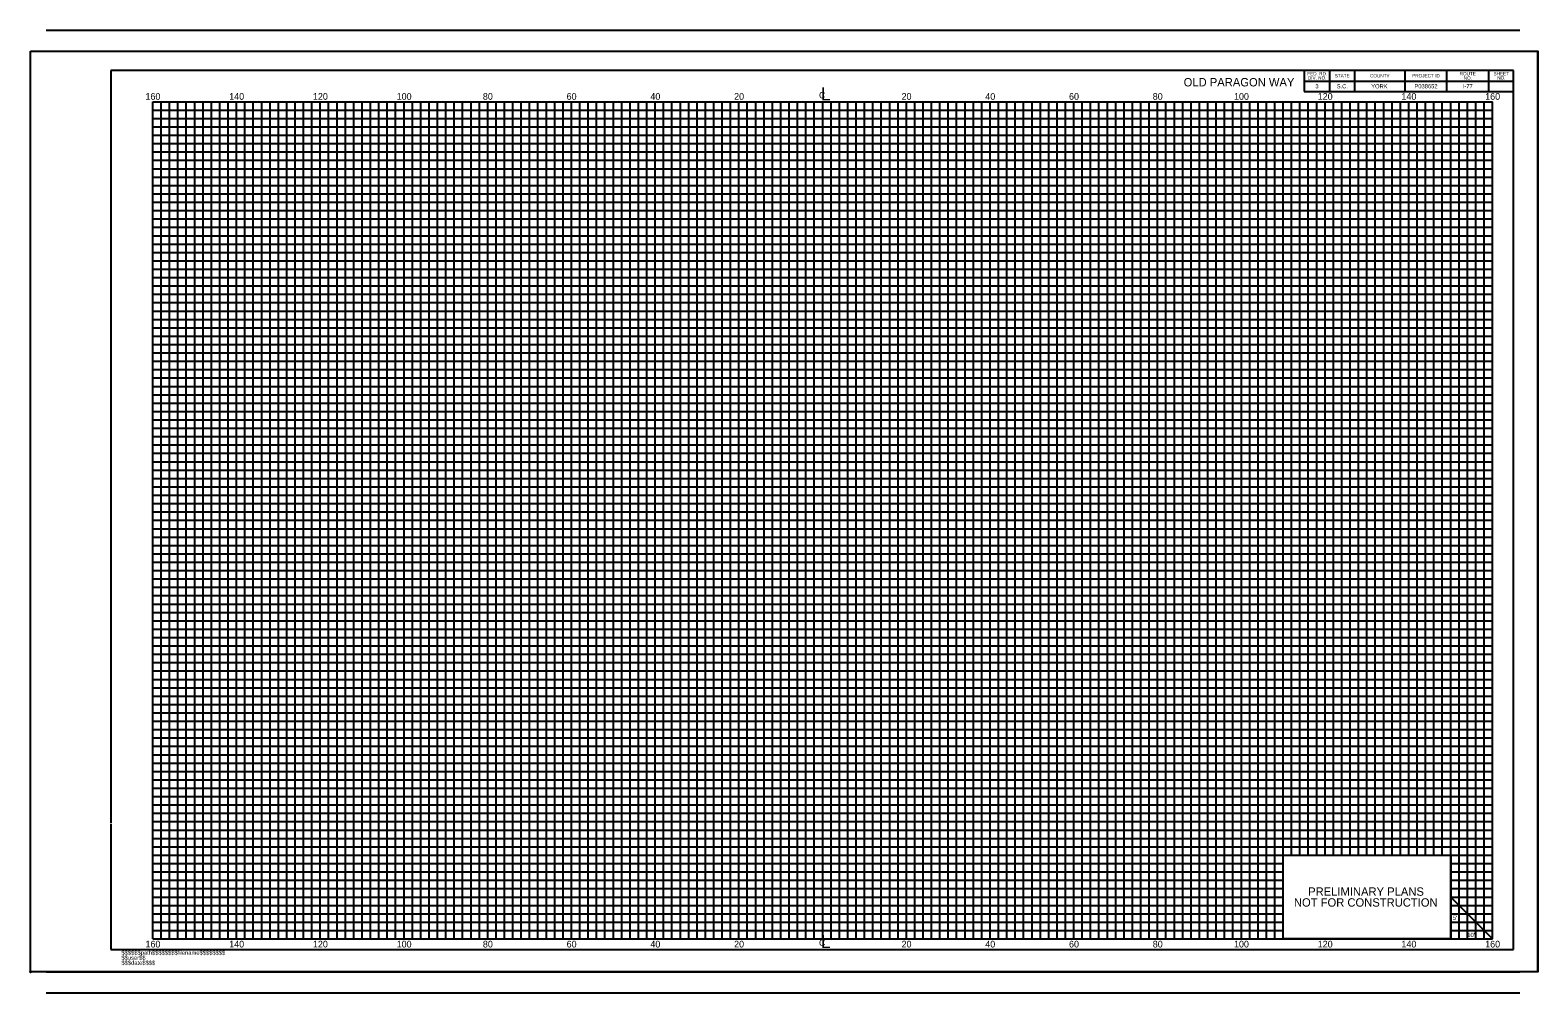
# Model space of a CAD drawing. Extents: x -15 to 165, y -6 to 109.
import ezdxf

# ---------------------------------------------------------------- set-up
doc = ezdxf.new("R2010")
doc.units = 0
for name, color, linetype in [('RD_DDB_StaTX', 7, 'Continuous'), ('RD_SHT_Bndy', 7, 'Continuous'), ('RD_SHT_ID', 7, 'Continuous'), ('RD_SHT_IplotShp', 7, 'Continuous'), ('RD_SHT_MjGrid_XS', 7, 'Continuous'), ('RD_SHT_MnGrid_XS', 7, 'Continuous'), ('RD_SHT_Snap', 7, 'Continuous'), ('RD_SHT_TX', 7, 'Continuous')]:
    doc.layers.add(name, color=color, linetype=linetype)

msp = doc.modelspace()

# ---------------------------------------------------------------- linework, layer by layer
at = {"layer": 'RD_SHT_Bndy'}
for p, q in [((-12.73, 108.55), (163.27, 108.55)), ((-12.73, 106.05), (163.27, 106.05)), ((-5, 103.72), (-5, 13.81)), ((162.51, 103.72), (-5, 103.72)), ((137.51, 103.72), (137.51, 101.22)), ((140.51, 103.72), (140.51, 101.22)), ((143.51, 103.72), (143.51, 101.22)), ((149.51, 103.72), (149.51, 101.22)), ((154.51, 103.72), (154.51, 101.22)), ((159.51, 103.72), (159.51, 101.22)), ((162.51, -1.28), (162.51, 103.72)), ((137.51, 102.47), (162.51, 102.47)), ((137.51, 101.22), (162.51, 101.22)), ((-5, 13.72), (-5, -1.28)), ((139.95, 5), (139.95, 5)), ((145, 5), (145, 5)), ((-5, -1.28), (162.51, -1.28)), ((-12.73, -3.95), (163.27, -3.95)), ((-12.73, -6.45), (163.27, -6.45))]:
    msp.add_line(p, q, dxfattribs=at)
msp.add_lwpolyline([(135, 10), (155, 10), (155, 0), (135, 0)], close=True, dxfattribs=at)
at = {"layer": 'RD_SHT_IplotShp'}
msp.add_lwpolyline([(-14.59, 106.05), (165.41, 106.05), (165.41, -3.95), (-14.59, -3.95)], close=True, dxfattribs=at)
at = {"layer": 'RD_SHT_MjGrid_XS'}
for p, q in [((0, 100), (160, 100)), ((0, 0), (0, 100)), ((5, 0), (5, 100)), ((10, 0), (10, 100)), ((15, 0), (15, 100)), ((20, 0), (20, 100)), ((25, 0), (25, 100)), ((30, 0), (30, 100)), ((35, 0), (35, 100)), ((40, 0), (40, 100)), ((45, 0), (45, 100)), ((50, 0), (50, 100)), ((55, 0), (55, 100)), ((60, 0), (60, 100)), ((65, 0), (65, 100)), ((70, 0), (70, 100)), ((75, 0), (75, 100)), ((80, 0), (80, 100)), ((85, 0), (85, 100)), ((90, 0), (90, 100)), ((95, 0), (95, 100)), ((100, 0), (100, 100)), ((105, 0), (105, 100)), ((110, 0), (110, 100)), ((115, 0), (115, 100)), ((120, 0), (120, 100)), ((125, 0), (125, 100)), ((130, 0), (130, 100)), ((135, 0), (135, 100)), ((140, 10), (140, 100)), ((145, 10), (145, 100)), ((150, 10), (150, 100)), ((155, 0), (155, 100)), ((160, 0), (160, 100)), ((0, 95), (160, 95)), ((0, 90), (160, 90)), ((0, 85), (160, 85)), ((0, 80), (160, 80)), ((0, 75), (160, 75)), ((0, 70), (160, 70)), ((0, 65), (160, 65)), ((0, 60), (160, 60)), ((0, 55), (160, 55)), ((0, 50), (160, 50)), ((0, 45), (160, 45)), ((0, 40), (160, 40)), ((0, 35), (160, 35)), ((0, 30), (160, 30)), ((0, 25), (160, 25)), ((0, 20), (160, 20)), ((0, 15), (160, 15)), ((0, 10), (160, 10)), ((0, 5), (135, 5)), ((155, 5), (160, 0)), ((155, 5), (160, 5)), ((0, 0), (160, 0))]:
    msp.add_line(p, q, dxfattribs=at)
at = {"layer": 'RD_SHT_MnGrid_XS'}
for p, q in [((1, 0), (1, 100)), ((2, 0), (2, 100)), ((3, 0), (3, 100)), ((4, 0), (4, 100)), ((6, 0), (6, 100)), ((7, 0), (7, 100)), ((8, 0), (8, 100)), ((9, 0), (9, 100)), ((11, 0), (11, 100)), ((12, 0), (12, 100)), ((13, 0), (13, 100)), ((14, 0), (14, 100)), ((16, 0), (16, 100)), ((17, 0), (17, 100)), ((18, 0), (18, 100)), ((19, 0), (19, 100)), ((21, 0), (21, 100)), ((22, 0), (22, 100)), ((23, 0), (23, 100)), ((24, 0), (24, 100)), ((26, 0), (26, 100)), ((27, 0), (27, 100)), ((28, 0), (28, 100)), ((29, 0), (29, 100)), ((31, 0), (31, 100)), ((32, 0), (32, 100)), ((33, 0), (33, 100)), ((34, 0), (34, 100)), ((36, 0), (36, 100)), ((37, 0), (37, 100)), ((38, 0), (38, 100)), ((39, 0), (39, 100)), ((41, 0), (41, 100)), ((42, 0), (42, 100)), ((43, 0), (43, 100)), ((44, 0), (44, 100)), ((46, 0), (46, 100)), ((47, 0), (47, 100)), ((48, 0), (48, 100)), ((49, 0), (49, 100)), ((51, 0), (51, 100)), ((52, 0), (52, 100)), ((53, 0), (53, 100)), ((54, 0), (54, 100)), ((56, 0), (56, 100)), ((57, 0), (57, 100)), ((58, 0), (58, 100)), ((59, 0), (59, 100)), ((61, 0), (61, 100)), ((62, 0), (62, 100)), ((63, 0), (63, 100)), ((64, 0), (64, 100)), ((66, 0), (66, 100)), ((67, 0), (67, 100)), ((68, 0), (68, 100)), ((69, 0), (69, 100)), ((71, 0), (71, 100)), ((72, 0), (72, 100)), ((73, 0), (73, 100)), ((74, 0), (74, 100)), ((76, 0), (76, 100)), ((77, 0), (77, 100)), ((78, 0), (78, 100)), ((79, 0), (79, 100)), ((81, 0), (81, 100)), ((82, 0), (82, 100)), ((83, 0), (83, 100)), ((84, 0), (84, 100)), ((86, 0), (86, 100)), ((87, 0), (87, 100)), ((88, 0), (88, 100)), ((89, 0), (89, 100)), ((91, 0), (91, 100)), ((92, 0), (92, 100)), ((93, 0), (93, 100)), ((94, 0), (94, 100)), ((96, 0), (96, 100)), ((97, 0), (97, 100)), ((98, 0), (98, 100)), ((99, 0), (99, 100)), ((101, 0), (101, 100)), ((102, 0), (102, 100)), ((103, 0), (103, 100)), ((104, 0), (104, 100)), ((106, 0), (106, 100)), ((107, 0), (107, 100)), ((108, 0), (108, 100)), ((109, 0), (109, 100)), ((111, 0), (111, 100)), ((112, 0), (112, 100)), ((113, 0), (113, 100)), ((114, 0), (114, 100)), ((116, 0), (116, 100)), ((117, 0), (117, 100)), ((118, 0), (118, 100)), ((119, 0), (119, 100)), ((121, 0), (121, 100)), ((122, 0), (122, 100)), ((123, 0), (123, 100)), ((124, 0), (124, 100)), ((126, 0), (126, 100)), ((127, 0), (127, 100)), ((128, 0), (128, 100)), ((129, 0), (129, 100)), ((131, 0), (131, 100)), ((132, 0), (132, 100)), ((133, 0), (133, 100)), ((134, 0), (134, 100)), ((136, 10), (136, 100)), ((137, 10), (137, 100)), ((138, 10), (138, 100)), ((139, 10), (139, 100)), ((141, 10), (141, 100)), ((142, 10), (142, 100)), ((143, 10), (143, 100)), ((144, 10), (144, 100)), ((146, 10), (146, 100)), ((147, 10), (147, 100)), ((148, 10), (148, 100)), ((149, 10), (149, 100)), ((151, 10), (151, 100)), ((152, 10), (152, 100)), ((153, 10), (153, 100)), ((154, 10), (154, 100)), ((156, 0), (156, 100)), ((157, 0), (157, 100)), ((158, 0), (158, 100)), ((159, 0), (159, 100)), ((0, 99), (160, 99)), ((0, 98), (160, 98)), ((0, 97), (160, 97)), ((0, 96), (160, 96)), ((0, 94), (160, 94)), ((0, 93), (160, 93)), ((0, 92), (160, 92)), ((0, 91), (160, 91)), ((0, 89), (160, 89)), ((0, 88), (160, 88)), ((0, 87), (160, 87)), ((0, 86), (160, 86)), ((0, 84), (160, 84)), ((0, 83), (160, 83)), ((0, 82), (160, 82)), ((0, 81), (160, 81)), ((0, 79), (160, 79)), ((0, 78), (160, 78)), ((0, 77), (160, 77)), ((0, 76), (160, 76)), ((0, 74), (160, 74)), ((0, 73), (160, 73)), ((0, 72), (160, 72)), ((0, 71), (160, 71)), ((0, 69), (160, 69)), ((0, 68), (160, 68)), ((0, 67), (160, 67)), ((0, 66), (160, 66)), ((0, 64), (160, 64)), ((0, 63), (160, 63)), ((0, 62), (160, 62)), ((0, 61), (160, 61)), ((0, 59), (160, 59)), ((0, 58), (160, 58)), ((0, 57), (160, 57)), ((0, 56), (160, 56)), ((0, 54), (160, 54)), ((0, 53), (160, 53)), ((0, 52), (160, 52)), ((0, 51), (160, 51)), ((0, 49), (160, 49)), ((0, 48), (160, 48)), ((0, 47), (160, 47)), ((0, 46), (160, 46)), ((0, 44), (160, 44)), ((0, 43), (160, 43)), ((0, 42), (160, 42)), ((0, 41), (160, 41)), ((0, 39), (160, 39)), ((0, 38), (160, 38)), ((0, 37), (160, 37)), ((0, 36), (160, 36)), ((0, 34), (160, 34)), ((0, 33), (160, 33)), ((0, 32), (160, 32)), ((0, 31), (160, 31)), ((0, 29), (160, 29)), ((0, 28), (160, 28)), ((0, 27), (160, 27)), ((0, 26), (160, 26)), ((0, 24), (160, 24)), ((0, 23), (160, 23)), ((0, 22), (160, 22)), ((0, 21), (160, 21)), ((0, 21), (160, 21)), ((0, 19), (160, 19)), ((0, 18), (160, 18)), ((0, 17), (160, 17)), ((0, 16), (160, 16)), ((0, 14), (160, 14)), ((0, 13), (160, 13)), ((0, 12), (160, 12)), ((0, 11), (160, 11)), ((0, 9), (135, 9)), ((0, 8), (135, 8)), ((155, 9), (160, 9)), ((155, 8), (160, 8)), ((0, 7), (135, 7)), ((0, 6), (135, 6)), ((155, 7), (160, 7)), ((155, 6), (160, 6)), ((0, 4), (135, 4)), ((155, 4), (160, 4)), ((0, 3), (135, 3)), ((0, 2), (135, 2)), ((155, 3), (160, 3)), ((155, 2), (160, 2)), ((0, 1), (135, 1)), ((155, 1), (160, 1))]:
    msp.add_line(p, q, dxfattribs=at)
at = {"layer": 'RD_SHT_Snap'}
for p, q in [((-14.59, -3.95), (-14.59, 106.05)), ((165.41, -3.95), (165.41, 106.05))]:
    msp.add_line(p, q, dxfattribs=at)
msp.add_circle((-14.59, -3.95), 0.0607, dxfattribs=at)

# ---------------------------------------------------------------- texts
at = {"layer": 'RD_DDB_StaTX'}
for s, height, p in [('160', 0.8, (-0.88, 100.23)), ('140', 0.8, (9.12, 100.23)), ('120', 0.8, (19.12, 100.23)), ('100', 0.8, (29.12, 100.23)), ('80', 0.8, (39.42, 100.23)), ('60', 0.8, (49.42, 100.23)), ('40', 0.8, (59.42, 100.23)), ('20', 0.8, (69.42, 100.23)), ('C', 0.773, (79.56, 100.4)), ('L', 1.55, (79.79, 100.16)), ('20', 0.8, (89.42, 100.23)), ('40', 0.8, (99.42, 100.23)), ('60', 0.8, (109.42, 100.23)), ('80', 0.8, (119.42, 100.23)), ('100', 0.8, (129.12, 100.23)), ('120', 0.8, (139.12, 100.23)), ('140', 0.8, (149.12, 100.23)), ('160', 0.8, (159.12, 100.23)), ('L', 1.55, (79.79, -1.09)), ('160', 0.8, (-0.88, -1.03)), ('140', 0.8, (9.12, -1.03)), ('120', 0.8, (19.12, -1.03)), ('100', 0.8, (29.12, -1.03)), ('80', 0.8, (39.42, -1.03)), ('60', 0.8, (49.42, -1.03)), ('40', 0.8, (59.42, -1.03)), ('20', 0.8, (69.42, -1.03)), ('C', 0.773, (79.56, -0.85)), ('20', 0.8, (89.42, -1.03)), ('40', 0.8, (99.42, -1.03)), ('60', 0.8, (109.42, -1.03)), ('80', 0.8, (119.42, -1.03)), ('100', 0.8, (129.12, -1.03)), ('120', 0.8, (139.12, -1.03)), ('140', 0.8, (149.12, -1.03)), ('160', 0.8, (159.12, -1.03))]:
    msp.add_text(s, height=height, dxfattribs=at).set_placement(p)
at = {"layer": 'RD_SHT_ID'}
for s, p in [('$$$$$$path$$$$$$$$filename$$$$$$$$', (-3.75, -1.9)), ('$$user$$', (-3.75, -2.5)), ('$$$date$$$$', (-3.75, -3.1))]:
    msp.add_text(s, height=0.5, rotation=360, dxfattribs=at).set_placement(p)
at = {"layer": 'RD_SHT_TX'}
for s, height, p in [('OLD PARAGON WAY', 1, (123.11, 101.83)), ('FED. RD.', 0.4, (137.88, 103.15)), ('DIV. NO.', 0.4, (137.95, 102.65)), ('STATE', 0.4, (141.15, 102.9)), ('COUNTY', 0.4, (145.37, 102.9)), ('PROJECT ID', 0.4, (150.41, 102.9)), ('ROUTE', 0.4, (156.07, 103.15)), ('NO.', 0.4, (156.56, 102.63)), ('SHEET', 0.4, (160.12, 103.15)), ('NO.', 0.4, (160.56, 102.65)), ('3', 0.5, (138.84, 101.6)), ('S.C.', 0.5, (141.39, 101.6)), ('YORK', 0.5, (145.51, 101.6)), ('P038652', 0.5, (150.67, 101.6)), ('I-77', 0.5, (156.44, 101.6)), ('PRELIMINARY PLANS', 1, (137.98, 5.15)), ('NOT FOR CONSTRUCTION', 1, (136.28, 3.85)), ("5'", 0.512, (155.26, 2.26)), ("10'", 0.512, (156.97, 0.21))]:
    msp.add_text(s, height=height, dxfattribs=at).set_placement(p)

doc.saveas('drawing.dxf')
